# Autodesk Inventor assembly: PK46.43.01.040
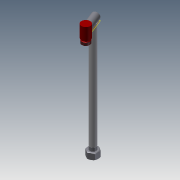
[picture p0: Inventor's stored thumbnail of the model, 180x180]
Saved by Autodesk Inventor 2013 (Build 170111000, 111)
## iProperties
Shininess: 64.0
Length Units: 11269
Angle Units: 11279
Time Units: 11290
Mass Units: 11283
Length Display Precision: 3
Angle Display Precision: 2
Compacted: True
Created: 2004-12
Part Number: PK46.43.01.040
Document SubType Name: Assembly
Designer: ELarisa
Manufacturer: Standard
Standards Organization: Custom
Density: 0.0
Volumn: 0.0
Area: 0.0
PropertySet Name: Model Information
Control State: 0
Master: False
Checked Out: False
Checked Out Date: 2008-10-09
Last Check In Date: 2008-10-09
Author: ELarisa
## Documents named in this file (6)
- D:\FrontLoaderVault\Data\Assy, Chassis, Front\PK46.43.01.040.iam
- D:\FrontLoaderVault\Data\Assy, Chassis, Front\PK46.43.01.017.ipt
- D:\FrontLoaderVault\Data\Assy, Chassis, Front\PK46.43.01.012.ipt
- D:\FrontLoaderVault\Data\Assy, Chassis, Front\027.08.00.004.ipt
- D:\FrontLoaderVault\Data\Assy, Chassis, Front\027.07.03.005.ipt
- D:\FrontLoaderVault\Data\Assy, Chassis, Front\027.04.04.012.ipt
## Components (5 placed, 5 different names)
1. PK46.43.01.017:1 — Insert:6
2. 027.08.00.004:1 — Insert:3, Angle:1
3. 027.07.03.005:1 — Insert:3, Insert:6
4. 027.04.04.012:1 — Insert:5, Angle:1
5. PK46.43.01.012:1 — Insert:5
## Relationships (4: Insert 3, Angle 1)
- Insert:3: 027.08.00.004:1 ↔ 027.07.03.005:1
- Insert:5: 027.04.04.012:1 ↔ PK46.43.01.012:1
- Angle:1: 027.08.00.004:1 ↔ 027.04.04.012:1
- Insert:6: PK46.43.01.017:1 ↔ 027.07.03.005:1
